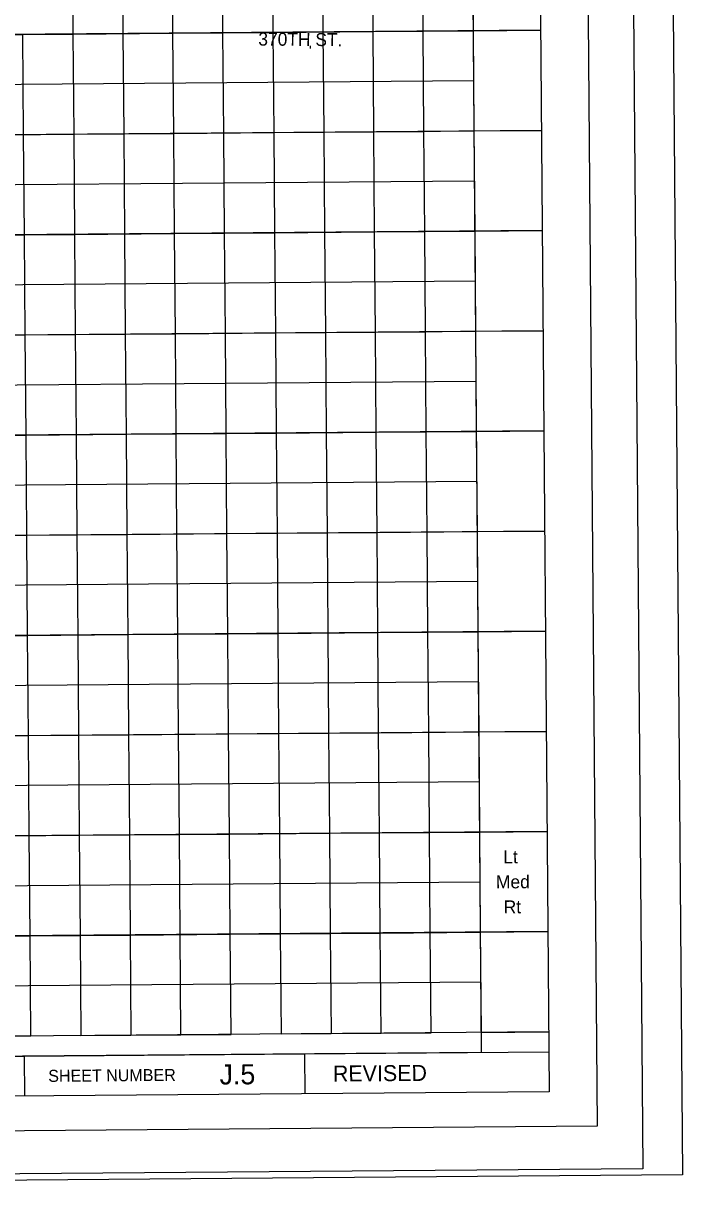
# Model space of a CAD drawing. Extents: x 11670159 to 11702568, y 9558247 to 9571922.
# Drawn here: x 11689347 to 11690664, y 9566402 to 9568756 of the extents above; entities that cross this region are included whole.
import ezdxf

# ---------------------------------------------------------------- set-up
doc = ezdxf.new("R2010")
doc.units = 0
for name, color, linetype in [('dsnNonPlotable', 7, 'Continuous'), ('DsnShtDBGLtRtTextLower', 7, 'Continuous'), ('DsnShtDBGMedTextLower', 7, 'Continuous'), ('DsnShtHorizMidLine', 7, 'Continuous'), ('DsnShtInsideBorder', 7, 'Continuous'), ('DsnShtMajorGrid01', 7, 'Continuous'), ('DsnShtMajorGrid02', 7, 'Continuous'), ('DsnShtMajorGrid03', 7, 'Continuous'), ('DsnShtMajorGrid04', 7, 'Continuous'), ('DsnShtMajorGrid05', 7, 'Continuous'), ('DsnShtMajorGrid06', 7, 'Continuous'), ('DsnShtMajorGrid07', 7, 'Continuous'), ('DsnShtMajorGrid08', 7, 'Continuous'), ('DsnShtMajorGrid09', 7, 'Continuous'), ('DsnShtMajorGrid10', 7, 'Continuous'), ('DsnShtMajorGrid11', 7, 'Continuous'), ('DsnShtMinorGrid01', 7, 'Continuous'), ('DsnShtMinorGrid02', 7, 'Continuous'), ('DsnShtMinorGrid03', 7, 'Continuous'), ('DsnShtMinorGrid04', 7, 'Continuous'), ('DsnShtMinorGrid05', 7, 'Continuous'), ('DsnShtMinorGrid06', 7, 'Continuous'), ('DsnShtMinorGrid07', 7, 'Continuous'), ('DsnShtMinorGrid08', 7, 'Continuous'), ('DsnShtMinorGrid09', 7, 'Continuous'), ('DsnShtMinorGrid10', 7, 'Continuous'), ('DsnShtMinorGrid11', 7, 'Continuous'), ('DsnShtOutsideBorder', 7, 'Continuous'), ('DsnShtPlotShape', 7, 'Continuous'), ('dsnShtPlotShapeBatchPrint', 7, 'Continuous'), ('DsnShtRevisedText', 7, 'Continuous'), ('dsnTextCpn', 7, 'Continuous'), ('dsnTextFinalPlan', 7, 'Continuous'), ('hwyPlanSheetShape', 7, 'Continuous')]:
    doc.layers.add(name, color=color, linetype=linetype)

msp = doc.modelspace()

# ---------------------------------------------------------------- linework, layer by layer
at = {"layer": 'dsnNonPlotable'}
msp.add_line((11689919.9, 9568711.3), (11689919.9, 9568706.4), dxfattribs=at)
msp.add_lwpolyline([(11684229.4, 9570693), (11690229.2, 9570741.4), (11690261.8, 9566701.6), (11684262, 9566653.2)], close=True, dxfattribs=at)
at = {"layer": 'DsnShtHorizMidLine'}
msp.add_line((11684110.5, 9568692), (11690380.3, 9568742.6), dxfattribs=at)
at = {"layer": 'DsnShtInsideBorder'}
msp.add_line((11689348.3, 9566694.2), (11689349, 9566614.2), dxfattribs=at)
at = {"layer": 'DsnShtMajorGrid01'}
for points in [[(11690394.8, 9566942.6), (11684125, 9566892.1)], [(11689259.9, 9566933.5), (11689459.9, 9566935.1), (11689461.5, 9566735.1), (11689661.5, 9566736.7), (11689659.9, 9566936.7), (11689859.9, 9566938.3), (11689861.5, 9566738.3), (11690061.5, 9566739.9), (11690059.8, 9566939.9), (11690259.8, 9566941.5), (11690261.5, 9566741.5), (11690396.5, 9566742.6), (11684126.7, 9566692.1)]]:
    msp.add_lwpolyline(points, dxfattribs=at)
at = {"layer": 'DsnShtMajorGrid02'}
for points in [[(11690393.2, 9567142.6), (11684123.4, 9567092.1)], [(11689258.3, 9567133.5), (11689458.3, 9567135.1), (11689459.9, 9566935.1), (11689659.9, 9566936.7), (11689658.2, 9567136.7), (11689858.2, 9567138.3), (11689859.9, 9566938.3), (11690059.8, 9566939.9), (11690058.2, 9567139.9), (11690258.2, 9567141.5), (11690259.8, 9566941.5), (11690394.8, 9566942.6), (11684125, 9566892.1)]]:
    msp.add_lwpolyline(points, dxfattribs=at)
at = {"layer": 'DsnShtMajorGrid03'}
for points in [[(11690391.6, 9567342.6), (11684121.8, 9567292)], [(11689256.6, 9567333.5), (11689456.6, 9567335.1), (11689458.3, 9567135.1), (11689658.2, 9567136.7), (11689656.6, 9567336.7), (11689856.6, 9567338.3), (11689858.2, 9567138.3), (11690058.2, 9567139.9), (11690056.6, 9567339.9), (11690256.6, 9567341.5), (11690258.2, 9567141.5), (11690393.2, 9567142.6), (11684123.4, 9567092.1)]]:
    msp.add_lwpolyline(points, dxfattribs=at)
at = {"layer": 'DsnShtMajorGrid04'}
for points in [[(11690390, 9567542.6), (11684120.2, 9567492)], [(11689255, 9567533.5), (11689455, 9567535.1), (11689456.6, 9567335.1), (11689656.6, 9567336.7), (11689655, 9567536.7), (11689855, 9567538.3), (11689856.6, 9567338.3), (11690056.6, 9567339.9), (11690055, 9567539.9), (11690255, 9567541.5), (11690256.6, 9567341.5), (11690391.6, 9567342.6), (11684121.8, 9567292)]]:
    msp.add_lwpolyline(points, dxfattribs=at)
at = {"layer": 'DsnShtMajorGrid05'}
for points in [[(11690388.4, 9567742.6), (11684118.6, 9567692)], [(11689253.4, 9567733.5), (11689453.4, 9567735.1), (11689455, 9567535.1), (11689655, 9567536.7), (11689653.4, 9567736.7), (11689853.4, 9567738.3), (11689855, 9567538.3), (11690055, 9567539.9), (11690053.4, 9567739.9), (11690253.4, 9567741.5), (11690255, 9567541.5), (11690390, 9567542.6), (11684120.2, 9567492)]]:
    msp.add_lwpolyline(points, dxfattribs=at)
at = {"layer": 'DsnShtMajorGrid06'}
for points in [[(11690386.8, 9567942.6), (11684117, 9567892)], [(11689251.8, 9567933.4), (11689451.8, 9567935.1), (11689453.4, 9567735.1), (11689653.4, 9567736.7), (11689651.8, 9567936.7), (11689851.8, 9567938.3), (11689853.4, 9567738.3), (11690053.4, 9567739.9), (11690051.8, 9567939.9), (11690251.8, 9567941.5), (11690253.4, 9567741.5), (11690388.4, 9567742.6), (11684118.6, 9567692)]]:
    msp.add_lwpolyline(points, dxfattribs=at)
at = {"layer": 'DsnShtMajorGrid07'}
for points in [[(11690385.2, 9568142.6), (11684115.4, 9568092)], [(11689250.2, 9568133.4), (11689450.2, 9568135.1), (11689451.8, 9567935.1), (11689651.8, 9567936.7), (11689650.2, 9568136.7), (11689850.2, 9568138.3), (11689851.8, 9567938.3), (11690051.8, 9567939.9), (11690050.2, 9568139.9), (11690250.2, 9568141.5), (11690251.8, 9567941.5), (11690386.8, 9567942.6), (11684117, 9567892)]]:
    msp.add_lwpolyline(points, dxfattribs=at)
at = {"layer": 'DsnShtMajorGrid08'}
for points in [[(11690383.5, 9568342.6), (11684113.7, 9568292)], [(11689248.6, 9568333.4), (11689448.6, 9568335), (11689450.2, 9568135.1), (11689650.2, 9568136.7), (11689648.6, 9568336.7), (11689848.6, 9568338.3), (11689850.2, 9568138.3), (11690050.2, 9568139.9), (11690048.6, 9568339.9), (11690248.6, 9568341.5), (11690250.2, 9568141.5), (11690385.2, 9568142.6), (11684115.4, 9568092)]]:
    msp.add_lwpolyline(points, dxfattribs=at)
at = {"layer": 'DsnShtMajorGrid09'}
for points in [[(11690381.9, 9568542.6), (11684112.1, 9568492)], [(11689247, 9568533.4), (11689447, 9568535), (11689448.6, 9568335), (11689648.6, 9568336.7), (11689647, 9568536.7), (11689846.9, 9568538.3), (11689848.6, 9568338.3), (11690048.6, 9568339.9), (11690046.9, 9568539.9), (11690246.9, 9568541.5), (11690248.6, 9568341.5), (11690383.5, 9568342.6), (11684113.7, 9568292)]]:
    msp.add_lwpolyline(points, dxfattribs=at)
at = {"layer": 'DsnShtMajorGrid10'}
for points in [[(11690380.3, 9568742.6), (11684110.5, 9568692)], [(11689245.4, 9568733.4), (11689445.3, 9568735), (11689447, 9568535), (11689647, 9568536.7), (11689645.3, 9568736.6), (11689845.3, 9568738.3), (11689846.9, 9568538.3), (11690046.9, 9568539.9), (11690045.3, 9568739.9), (11690245.3, 9568741.5), (11690246.9, 9568541.5), (11690381.9, 9568542.6), (11684112.1, 9568492)]]:
    msp.add_lwpolyline(points, dxfattribs=at)
at = {"layer": 'DsnShtMajorGrid11'}
for points in [[(11690243.7, 9568941.5), (11690245.3, 9568741.5), (11690380.3, 9568742.6), (11684110.5, 9568692)], [(11689443.7, 9568935), (11689445.3, 9568735), (11689645.3, 9568736.6), (11689643.7, 9568936.6)], [(11689843.7, 9568938.3), (11689845.3, 9568738.3), (11690045.3, 9568739.9), (11690043.7, 9568939.9)]]:
    msp.add_lwpolyline(points, dxfattribs=at)
at = {"layer": 'DsnShtMinorGrid01'}
for points in [[(11689161.5, 9566732.7), (11689361.5, 9566734.3), (11689359.9, 9566934.3), (11689559.9, 9566935.9), (11689561.5, 9566735.9), (11689761.5, 9566737.5), (11689759.9, 9566937.5), (11689959.9, 9566939.1), (11689961.5, 9566739.1), (11690161.5, 9566740.7), (11690159.8, 9566940.7)], [(11690260.6, 9566841.5), (11684260.8, 9566793.1)]]:
    msp.add_lwpolyline(points, dxfattribs=at)
at = {"layer": 'DsnShtMinorGrid02'}
for points in [[(11689159.9, 9566932.7), (11689359.9, 9566934.3), (11689358.3, 9567134.3), (11689558.3, 9567135.9), (11689559.9, 9566935.9), (11689759.9, 9566937.5), (11689758.2, 9567137.5), (11689958.2, 9567139.1), (11689959.9, 9566939.1), (11690159.8, 9566940.7), (11690158.2, 9567140.7)], [(11690259, 9567041.5), (11684259.2, 9566993.1)]]:
    msp.add_lwpolyline(points, dxfattribs=at)
at = {"layer": 'DsnShtMinorGrid03'}
for points in [[(11689158.3, 9567132.7), (11689358.3, 9567134.3), (11689356.6, 9567334.3), (11689556.6, 9567335.9), (11689558.3, 9567135.9), (11689758.2, 9567137.5), (11689756.6, 9567337.5), (11689956.6, 9567339.1), (11689958.2, 9567139.1), (11690158.2, 9567140.7), (11690156.6, 9567340.7)], [(11690257.4, 9567241.5), (11684257.6, 9567193.1)]]:
    msp.add_lwpolyline(points, dxfattribs=at)
at = {"layer": 'DsnShtMinorGrid04'}
for points in [[(11689156.7, 9567332.7), (11689356.6, 9567334.3), (11689355, 9567534.3), (11689555, 9567535.9), (11689556.6, 9567335.9), (11689756.6, 9567337.5), (11689755, 9567537.5), (11689955, 9567539.1), (11689956.6, 9567339.1), (11690156.6, 9567340.7), (11690155, 9567540.7)], [(11690255.8, 9567441.5), (11684256, 9567393.1)]]:
    msp.add_lwpolyline(points, dxfattribs=at)
at = {"layer": 'DsnShtMinorGrid05'}
for points in [[(11689155, 9567532.7), (11689355, 9567534.3), (11689353.4, 9567734.3), (11689553.4, 9567735.9), (11689555, 9567535.9), (11689755, 9567537.5), (11689753.4, 9567737.5), (11689953.4, 9567739.1), (11689955, 9567539.1), (11690155, 9567540.7), (11690153.4, 9567740.7)], [(11690254.2, 9567641.5), (11684254.4, 9567593.1)]]:
    msp.add_lwpolyline(points, dxfattribs=at)
at = {"layer": 'DsnShtMinorGrid06'}
for points in [[(11689153.4, 9567732.6), (11689353.4, 9567734.3), (11689351.8, 9567934.3), (11689551.8, 9567935.9), (11689553.4, 9567735.9), (11689753.4, 9567737.5), (11689751.8, 9567937.5), (11689951.8, 9567939.1), (11689953.4, 9567739.1), (11690153.4, 9567740.7), (11690151.8, 9567940.7)], [(11690252.6, 9567841.5), (11684252.8, 9567793.1)]]:
    msp.add_lwpolyline(points, dxfattribs=at)
at = {"layer": 'DsnShtMinorGrid07'}
for points in [[(11689151.8, 9567932.6), (11689351.8, 9567934.3), (11689350.2, 9568134.2), (11689550.2, 9568135.9), (11689551.8, 9567935.9), (11689751.8, 9567937.5), (11689750.2, 9568137.5), (11689950.2, 9568139.1), (11689951.8, 9567939.1), (11690151.8, 9567940.7), (11690150.2, 9568140.7)], [(11690251, 9568041.5), (11684251.2, 9567993.1)]]:
    msp.add_lwpolyline(points, dxfattribs=at)
at = {"layer": 'DsnShtMinorGrid08'}
for points in [[(11689150.2, 9568132.6), (11689350.2, 9568134.2), (11689348.6, 9568334.2), (11689548.6, 9568335.9), (11689550.2, 9568135.9), (11689750.2, 9568137.5), (11689748.6, 9568337.5), (11689948.6, 9568339.1), (11689950.2, 9568139.1), (11690150.2, 9568140.7), (11690148.6, 9568340.7)], [(11690249.4, 9568241.5), (11684249.6, 9568193.1)]]:
    msp.add_lwpolyline(points, dxfattribs=at)
at = {"layer": 'DsnShtMinorGrid09'}
for points in [[(11689148.6, 9568332.6), (11689348.6, 9568334.2), (11689347, 9568534.2), (11689547, 9568535.8), (11689548.6, 9568335.9), (11689748.6, 9568337.5), (11689747, 9568537.5), (11689946.9, 9568539.1), (11689948.6, 9568339.1), (11690148.6, 9568340.7), (11690146.9, 9568540.7)], [(11690247.7, 9568441.5), (11684247.9, 9568393.1)]]:
    msp.add_lwpolyline(points, dxfattribs=at)
at = {"layer": 'DsnShtMinorGrid10'}
for points in [[(11689147, 9568532.6), (11689347, 9568534.2), (11689345.4, 9568734.2), (11689545.3, 9568735.8), (11689547, 9568535.8), (11689747, 9568537.5), (11689745.3, 9568737.5), (11689945.3, 9568739.1), (11689946.9, 9568539.1), (11690146.9, 9568540.7), (11690145.3, 9568740.7)], [(11690246.1, 9568641.5), (11684246.3, 9568593.1)]]:
    msp.add_lwpolyline(points, dxfattribs=at)
at = {"layer": 'DsnShtMinorGrid11'}
for points in [[(11689543.7, 9568935.8), (11689545.3, 9568735.8), (11689745.3, 9568737.5), (11689743.7, 9568937.4)], [(11689943.7, 9568939.1), (11689945.3, 9568739.1), (11690145.3, 9568740.7), (11690143.7, 9568940.7)]]:
    msp.add_lwpolyline(points, dxfattribs=at)
at = {"layer": 'DsnShtOutsideBorder'}
for p, q in [((11687859.9, 9566682.2), (11689348.3, 9566694.2)), ((11689348.3, 9566694.2), (11689908.3, 9566698.7)), ((11689348.3, 9566694.2), (11689349, 9566614.2)), ((11689908.3, 9566698.7), (11690396.8, 9566702.6)), ((11689908.3, 9566698.7), (11689908.9, 9566618.7))]:
    msp.add_line(p, q, dxfattribs=at)
msp.add_lwpolyline([(11684094.4, 9570691.9), (11690364.2, 9570742.5), (11690397.4, 9566622.6), (11684127.6, 9566572.1)], close=True, dxfattribs=at)
at = {"layer": 'DsnShtPlotShape'}
msp.add_lwpolyline([(11683828.5, 9570801.8), (11690628.3, 9570856.6), (11690663.8, 9566456.8), (11683864, 9566401.9)], close=True, dxfattribs=at)
at = {"layer": 'dsnShtPlotShapeBatchPrint'}
msp.add_lwpolyline([(11683907.6, 9570802.4), (11690549.2, 9570856), (11690584.6, 9566469.3), (11683943, 9566415.7)], close=True, dxfattribs=at)
at = {"layer": 'hwyPlanSheetShape'}
msp.add_lwpolyline([(11683998.8, 9570760.1), (11690458.6, 9570812.2), (11690493, 9566554), (11684033.2, 9566501.9)], close=True, dxfattribs=at)

# ---------------------------------------------------------------- texts
at = {"layer": 'DsnShtDBGLtRtTextLower'}
for s, p in [('Lt', (11690305.8, 9567078.9)), ('Rt', (11690306.6, 9566978.9))]:
    msp.add_text(s, height=26, rotation=0.4622, dxfattribs=at).set_placement(p)
at = {"layer": 'DsnShtDBGMedTextLower'}
msp.add_text('Med', height=26, rotation=0.4622, dxfattribs=at).set_placement((11690291.1, 9567028.8))
at = {"layer": 'DsnShtInsideBorder'}
msp.add_text('SHEET NUMBER   ', height=24, rotation=0.4622, dxfattribs=at).set_placement((11689396.2, 9566642.6))
at = {"layer": 'DsnShtRevisedText'}
msp.add_text('REVISED', height=32, rotation=0.4622, dxfattribs=at).set_placement((11689965.3, 9566643.2))
at = {"layer": 'dsnTextCpn'}
msp.add_text('J.5', height=40, rotation=0.4622, dxfattribs=at).set_placement((11689738.8, 9566637.3))
at = {"layer": 'dsnTextFinalPlan'}
msp.add_text('370TH ST.', height=26, rotation=359.5147, dxfattribs=at).set_placement((11689816, 9568712.1))

doc.saveas('drawing.dxf')
